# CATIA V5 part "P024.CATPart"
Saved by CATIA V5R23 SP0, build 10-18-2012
Part number: 05-LICP-T02-E-S05-P024
Definition: Goupille elastique 5x75
Description: Goupille elastique ISO 8752 5x75
Bounding box of the stored display mesh (mm): x -75 to 0, y -2.5 to 2.49, z -2.498 to 2.498
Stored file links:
  C:\wamp\www\COURS\CONCEPTION GMP1\TITRE 02-SEMESTRE 2\03-TP7-PRESSE MECANIQUE\eleve\P024.CATPart
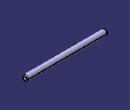
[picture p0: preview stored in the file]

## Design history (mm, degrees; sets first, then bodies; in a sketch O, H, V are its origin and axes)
Parameters
  Material = "St"
  d1_pin_nom_dia = 5 mm
  l_pin_length_nom = 75 mm
  d2_pin_id = 3.4 mm
  a_cham_max = 1.1 mm
  s_wall_th = 1 mm
  PartNumber = "Goupille elastique ISO 8752 5x75"
Set1
  Plane1: type Offset, RefPlane yz-plane, Offset 37.5, reversed
Body1 "PartBody" (main body)
  Sketch1 on zx-plane, origin (0, 0, 0), H (-1, 0, 0), V (0, 0, 1)
    point P1 (0, 2.2053)
    line L1 (0, 2.2053) -> (1.1, 2.5)
    point P2 (1.1, 2.5)
    point P3 (1.1, 2.5)
    line L2 (1.1, 2.5) -> (73.9, 2.5)
    point P4 (73.9, 2.5)
    line L3 (73.9, 2.5) -> (75, 2.2053)
    point P5 (75, 2.2053)
    point P6 (75, 2.2053)
    line L4 (75, 2.2053) -> (75, 1.5)
    line L5 (75, 1.5) -> (0, 1.5)
    line L6 (0, 1.5) -> (0, 2.2053)
    axis line L7 (-9.3888, 0) -> (37.524, 0)
    distance P1 L4 = 75 {= l_pin_length_nom}
    distance L5 L2 = 1 {= s_wall_th}
    angle L3 L2 = 15
    angle L1 L2 = 15
    distance L2 L7 = 2.5 {= d1_pin_nom_dia /2}
    distance V P2 = 1.1 {= a_cham_max}
    distance P4 P5 H = 1.1 {= a_cham_max}
    coincidence: P3 L1, P6 L3, P2 P3, P5 P6, P1 V
    horizontal: L2 H, L5 H, L7 H
    vertical: L4 V, L6 V
    fix: L7
  Shaft1: profile Sketch1, axis Sketch1.L7, angle 445, second angle -95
